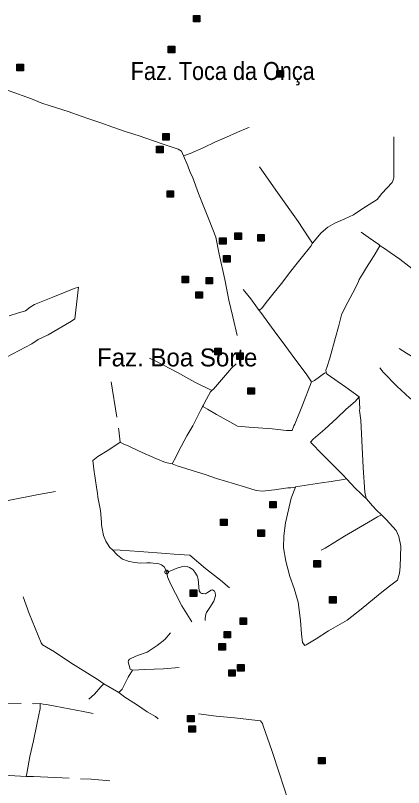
# Model space of a CAD drawing. Extents: x 393.5 to 446.9, y 8064.8 to 8120.4.
# Drawn here: x 404.99 to 408.44, y 8103.85 to 8110.72 of the extents above; entities that cross this region are included whole.
import ezdxf

# ---------------------------------------------------------------- set-up
doc = ezdxf.new("R2010")
doc.units = 0
doc.header["$LTSCALE"] = 0.064
doc.header["$PDMODE"] = 32
doc.header["$PDSIZE"] = 0.032
doc.linetypes.add('DOT_DASHED', pattern=[7.7, 5, -1.2, 0.3, -1.2])
doc.layers.add('2', color=7, linetype='Continuous', lineweight=25)
doc.layers.add('22', color=7, linetype='DOT_DASHED', lineweight=13)
doc.layers.add('61', color=7, linetype='Continuous')

msp = doc.modelspace()

# ---------------------------------------------------------------- hatches: boundary and pattern name
at = {"layer": '2'}
for points in [[(406.5725, 8110.7212), (406.6305, 8110.7212), (406.6305, 8110.6632), (406.5725, 8110.6632)], [(406.3481, 8110.4472), (406.4061, 8110.4472), (406.4061, 8110.3892), (406.3481, 8110.3892)], [(405.0009, 8110.2869), (405.0589, 8110.2869), (405.0589, 8110.2289), (405.0009, 8110.2289)], [(407.3152, 8110.2299), (407.3732, 8110.2299), (407.3732, 8110.1719), (407.3152, 8110.1719)], [(406.2995, 8109.6693), (406.3575, 8109.6693), (406.3575, 8109.6113), (406.2995, 8109.6113)], [(406.2434, 8109.557), (406.3014, 8109.557), (406.3014, 8109.499), (406.2434, 8109.499)], [(406.3382, 8109.1603), (406.3962, 8109.1603), (406.3962, 8109.1023), (406.3382, 8109.1023)], [(406.9409, 8108.7849), (406.9989, 8108.7849), (406.9989, 8108.7269), (406.9409, 8108.7269)], [(406.8043, 8108.7427), (406.8623, 8108.7427), (406.8623, 8108.6847), (406.8043, 8108.6847)], [(407.144, 8108.7706), (407.202, 8108.7706), (407.202, 8108.7126), (407.144, 8108.7126)], [(406.8404, 8108.5833), (406.8984, 8108.5833), (406.8984, 8108.5253), (406.8404, 8108.5253)], [(406.4713, 8108.3987), (406.5293, 8108.3987), (406.5293, 8108.3407), (406.4713, 8108.3407)], [(406.6849, 8108.3884), (406.7429, 8108.3884), (406.7429, 8108.3304), (406.6849, 8108.3304)], [(406.5937, 8108.2619), (406.6517, 8108.2619), (406.6517, 8108.2039), (406.5937, 8108.2039)], [(406.7619, 8107.7587), (406.8199, 8107.7587), (406.8199, 8107.7007), (406.7619, 8107.7007)], [(406.9581, 8107.7163), (407.0161, 8107.7163), (407.0161, 8107.6583), (406.9581, 8107.6583)], [(407.0561, 8107.407), (407.1141, 8107.407), (407.1141, 8107.349), (407.0561, 8107.349)], [(407.2518, 8106.3942), (407.3098, 8106.3942), (407.3098, 8106.3362), (407.2518, 8106.3362)], [(406.8131, 8106.2371), (406.8711, 8106.2371), (406.8711, 8106.1791), (406.8131, 8106.1791)], [(407.1464, 8106.1411), (407.2044, 8106.1411), (407.2044, 8106.0831), (407.1464, 8106.0831)], [(407.6446, 8105.8686), (407.7026, 8105.8686), (407.7026, 8105.8106), (407.6446, 8105.8106)], [(406.5431, 8105.607), (406.6011, 8105.607), (406.6011, 8105.549), (406.5431, 8105.549)], [(407.7832, 8105.5482), (407.8412, 8105.5482), (407.8412, 8105.4902), (407.7832, 8105.4902)], [(406.9878, 8105.357), (407.0458, 8105.357), (407.0458, 8105.299), (406.9878, 8105.299)], [(406.8443, 8105.2377), (406.9023, 8105.2377), (406.9023, 8105.1797), (406.8443, 8105.1797)], [(406.7987, 8105.1285), (406.8567, 8105.1285), (406.8567, 8105.0705), (406.7987, 8105.0705)], [(406.9656, 8104.942), (407.0236, 8104.942), (407.0236, 8104.884), (406.9656, 8104.884)], [(406.8863, 8104.8963), (406.9443, 8104.8963), (406.9443, 8104.8383), (406.8863, 8104.8383)], [(406.5196, 8104.4895), (406.5776, 8104.4895), (406.5776, 8104.4315), (406.5196, 8104.4315)], [(406.5313, 8104.3982), (406.5893, 8104.3982), (406.5893, 8104.3402), (406.5313, 8104.3402)], [(407.685, 8104.1159), (407.743, 8104.1159), (407.743, 8104.0579), (407.685, 8104.0579)]]:
    msp.add_hatch(color=256, dxfattribs=at).paths.add_polyline_path(points)

# ---------------------------------------------------------------- linework, layer by layer
for points in [[(406.5725, 8110.7212), (406.6305, 8110.7212), (406.6305, 8110.6632), (406.5725, 8110.6632)], [(406.3481, 8110.4472), (406.4061, 8110.4472), (406.4061, 8110.3892), (406.3481, 8110.3892)], [(405.0009, 8110.2869), (405.0589, 8110.2869), (405.0589, 8110.2289), (405.0009, 8110.2289)], [(407.3152, 8110.2299), (407.3732, 8110.2299), (407.3732, 8110.1719), (407.3152, 8110.1719)], [(406.2995, 8109.6693), (406.3575, 8109.6693), (406.3575, 8109.6113), (406.2995, 8109.6113)], [(406.2434, 8109.557), (406.3014, 8109.557), (406.3014, 8109.499), (406.2434, 8109.499)], [(406.3382, 8109.1603), (406.3962, 8109.1603), (406.3962, 8109.1023), (406.3382, 8109.1023)], [(406.9409, 8108.7849), (406.9989, 8108.7849), (406.9989, 8108.7269), (406.9409, 8108.7269)], [(406.8043, 8108.7427), (406.8623, 8108.7427), (406.8623, 8108.6847), (406.8043, 8108.6847)], [(407.144, 8108.7706), (407.202, 8108.7706), (407.202, 8108.7126), (407.144, 8108.7126)], [(406.8404, 8108.5833), (406.8984, 8108.5833), (406.8984, 8108.5253), (406.8404, 8108.5253)], [(406.4713, 8108.3987), (406.5293, 8108.3987), (406.5293, 8108.3407), (406.4713, 8108.3407)], [(406.6849, 8108.3884), (406.7429, 8108.3884), (406.7429, 8108.3304), (406.6849, 8108.3304)], [(406.5937, 8108.2619), (406.6517, 8108.2619), (406.6517, 8108.2039), (406.5937, 8108.2039)], [(406.7619, 8107.7587), (406.8199, 8107.7587), (406.8199, 8107.7007), (406.7619, 8107.7007)], [(406.9581, 8107.7163), (407.0161, 8107.7163), (407.0161, 8107.6583), (406.9581, 8107.6583)], [(407.0561, 8107.407), (407.1141, 8107.407), (407.1141, 8107.349), (407.0561, 8107.349)], [(407.2518, 8106.3942), (407.3098, 8106.3942), (407.3098, 8106.3362), (407.2518, 8106.3362)], [(406.8131, 8106.2371), (406.8711, 8106.2371), (406.8711, 8106.1791), (406.8131, 8106.1791)], [(407.1464, 8106.1411), (407.2044, 8106.1411), (407.2044, 8106.0831), (407.1464, 8106.0831)], [(407.6446, 8105.8686), (407.7026, 8105.8686), (407.7026, 8105.8106), (407.6446, 8105.8106)], [(406.5431, 8105.607), (406.6011, 8105.607), (406.6011, 8105.549), (406.5431, 8105.549)], [(407.7832, 8105.5482), (407.8412, 8105.5482), (407.8412, 8105.4902), (407.7832, 8105.4902)], [(406.9878, 8105.357), (407.0458, 8105.357), (407.0458, 8105.299), (406.9878, 8105.299)], [(406.8443, 8105.2377), (406.9023, 8105.2377), (406.9023, 8105.1797), (406.8443, 8105.1797)], [(406.7987, 8105.1285), (406.8567, 8105.1285), (406.8567, 8105.0705), (406.7987, 8105.0705)], [(406.9656, 8104.942), (407.0236, 8104.942), (407.0236, 8104.884), (406.9656, 8104.884)], [(406.8863, 8104.8963), (406.9443, 8104.8963), (406.9443, 8104.8383), (406.8863, 8104.8383)], [(406.5196, 8104.4895), (406.5776, 8104.4895), (406.5776, 8104.4315), (406.5196, 8104.4315)], [(406.5313, 8104.3982), (406.5893, 8104.3982), (406.5893, 8104.3402), (406.5313, 8104.3402)], [(407.685, 8104.1159), (407.743, 8104.1159), (407.743, 8104.0579), (407.685, 8104.0579)]]:
    msp.add_lwpolyline(points, close=True, dxfattribs=at)
at = {"layer": '22'}
for p, q in [((408.0468, 8107.3247), (408.0467, 8107.3262)), ((406.6529, 8107.24), (406.6548, 8107.2391)), ((406.3331, 8105.7669), (406.3336, 8105.7661)), ((405.7745, 8104.7708), (405.9083, 8104.6922)), ((405.6417, 8104.634), (405.6924, 8104.6772)), ((405.0845, 8103.947), (405.084, 8103.947))]:
    msp.add_line(p, q, dxfattribs=at)
for points in [[(406.0607, 8109.6581), (406.0233, 8109.6712), (405.9651, 8109.6881), (405.8537, 8109.7252), (405.7389, 8109.769), (405.6427, 8109.8011), (405.5735, 8109.8247), (405.457, 8109.8652), (405.2983, 8109.9175), (405.224, 8109.9411), (405.1312, 8109.9782), (404.9318, 8110.0502), (404.8896, 8110.067)], [(406.4851, 8109.471), (406.5419, 8109.4927), (406.6635, 8109.5467), (406.7614, 8109.5922), (406.8677, 8109.6378), (406.9589, 8109.6782), (407.0568, 8109.7204), (407.0669, 8109.7221)], [(406.3042, 8109.5761), (406.0811, 8109.6509), (406.0607, 8109.6581)], [(407.6308, 8108.693), (407.7091, 8108.787), (407.7681, 8108.8357), (407.8291, 8108.8723), (407.9186, 8108.9107), (407.9959, 8108.9473), (408.0447, 8108.9778), (408.1119, 8109.0245), (408.2059, 8109.0823), (408.2486, 8109.1351), (408.34, 8109.2345), (408.3522, 8109.2629), (408.3542, 8109.2812), (408.3563, 8109.3198), (408.3564, 8109.3745), (408.3565, 8109.6403)], [(406.4851, 8109.471), (406.4667, 8109.5114), (406.4363, 8109.5317), (406.3283, 8109.5654), (406.3042, 8109.5761)], [(406.5294, 8109.3649), (406.5233, 8109.381), (406.4851, 8109.471)], [(406.9609, 8107.8719), (406.9221, 8108.0389), (406.8883, 8108.1873), (406.8502, 8108.3718), (406.8023, 8108.5966), (406.7703, 8108.7468), (406.711, 8108.8971), (406.6169, 8109.1353), (406.5662, 8109.274), (406.5443, 8109.3263), (406.5294, 8109.3649)], [(407.159, 8109.3746), (407.3205, 8109.146), (407.5029, 8108.886), (407.5998, 8108.7418), (407.6308, 8108.693)], [(408.2326, 8108.6702), (408.2212, 8108.6807), (408.1265, 8108.7471), (408.0645, 8108.7916)], [(407.1566, 8108.0952), (407.1843, 8108.1188), (407.2316, 8108.1796), (407.2788, 8108.2403), (407.3666, 8108.3499), (407.4189, 8108.4174), (407.4713, 8108.4849), (407.5321, 8108.5591), (407.6165, 8108.667), (407.6308, 8108.693)], [(407.7526, 8107.5452), (407.7515, 8107.5639), (407.7578, 8107.5876), (407.7853, 8107.6699), (407.8365, 8107.8533), (407.8623, 8107.9497), (407.8885, 8108.0558), (407.9222, 8108.1232), (407.9897, 8108.2504), (408.0377, 8108.3451), (408.048, 8108.3713), (408.0775, 8108.4179), (408.1137, 8108.4766), (408.1599, 8108.5527), (408.1893, 8108.6001), (408.2323, 8108.6697), (408.2326, 8108.6702)], [(408.2326, 8108.6702), (408.2712, 8108.6457), (408.3228, 8108.6099), (408.4084, 8108.5514), (408.542, 8108.4464), (408.5883, 8108.4211), (408.639, 8108.387), (408.7159, 8108.3337), (408.7612, 8108.3029)], [(404.9089, 8107.6776), (405.1355, 8107.7987), (405.189, 8107.8348), (405.2787, 8107.8789), (405.4884, 8107.9989), (405.5168, 8108.0193), (405.5482, 8108.3023), (405.5105, 8108.2898), (405.3201, 8108.2143), (405.1572, 8108.1483), (405.1178, 8108.1247), (405.0785, 8108.0901), (405.0077, 8108.0697), (404.9322, 8108.0461)], [(407.1566, 8108.0952), (407.0817, 8108.1969), (407.031, 8108.2644), (407.0142, 8108.2813)], [(407.1566, 8108.0952), (407.1708, 8108.076), (407.29, 8107.9137), (407.3947, 8107.7752), (407.4746, 8107.6629), (407.5745, 8107.5294), (407.622, 8107.4583), (407.625, 8107.4597)], [(408.4043, 8107.7547), (408.4696, 8107.7146), (408.5968, 8107.6362), (408.643, 8107.6097)], [(406.1803, 8107.6703), (406.2365, 8107.644), (406.4295, 8107.5409), (406.5849, 8107.4567), (406.7358, 8107.3818)], [(406.9515, 8107.6188), (406.9115, 8107.5809), (406.7518, 8107.3948), (406.7383, 8107.3838), (406.7358, 8107.3818)], [(407.625, 8107.4597), (407.6482, 8107.4707), (407.739, 8107.5364), (407.7528, 8107.5414), (407.7526, 8107.5452)], [(408.0467, 8107.3262), (408.0467, 8107.3263), (407.9294, 8107.4129), (407.7628, 8107.5289), (407.7534, 8107.5407), (407.7528, 8107.5414)], [(408.2302, 8107.5827), (408.2614, 8107.5441), (408.3808, 8107.421), (408.4981, 8107.3142), (408.5664, 8107.2622), (408.6451, 8107.2207), (408.755, 8107.1806), (408.8753, 8107.1347), (409.0113, 8107.0785), (409.0133, 8107.0777)], [(405.8388, 8107.4601), (405.9081, 8107.0286), (405.919, 8106.9219)], [(407.4732, 8107.0811), (407.5429, 8107.2521), (407.622, 8107.4583)], [(406.7358, 8107.3818), (406.7238, 8107.3688), (406.6709, 8107.2725), (406.6619, 8107.2519), (406.6529, 8107.24)], [(407.9315, 8107.2149), (408.0109, 8107.2847), (408.0468, 8107.3247)], [(408.1109, 8106.4184), (408.1106, 8106.4214), (408.0967, 8106.478), (408.0819, 8106.6961), (408.07, 8106.9364), (408.0604, 8107.1175), (408.0508, 8107.2049), (408.0521, 8107.2211), (408.0468, 8107.3247)], [(406.6529, 8107.236), (406.6354, 8107.2042), (406.5654, 8107.0684), (406.5135, 8106.9785), (406.4395, 8106.8387), (406.4144, 8106.7895), (406.383, 8106.7303), (406.3822, 8106.7288)], [(406.6574, 8107.2442), (406.6563, 8107.2422), (406.6561, 8107.2418), (406.6553, 8107.2404), (406.6529, 8107.236)], [(406.6548, 8107.2391), (406.698, 8107.217), (406.7783, 8107.1682), (406.897, 8107.1035), (406.9629, 8107.0647), (406.9992, 8107.0631)], [(407.9323, 8106.5972), (407.9108, 8106.6215), (407.724, 8106.8106), (407.6141, 8106.9229), (407.6383, 8106.9496), (407.7422, 8107.0386), (407.8476, 8107.1366), (407.9315, 8107.2149)], [(406.9992, 8107.0631), (407.0641, 8107.0563), (407.2731, 8107.0423), (407.3996, 8107.0269), (407.4515, 8107.0269), (407.4664, 8107.067), (407.4732, 8107.0811)], [(405.919, 8106.9219), (405.8205, 8106.8535), (405.7223, 8106.7955), (405.6771, 8106.7593), (405.6897, 8106.6572)], [(406.3822, 8106.7288), (406.3229, 8106.7402), (406.2364, 8106.7777), (406.0891, 8106.8409), (405.9974, 8106.8861), (405.9461, 8106.9064), (405.9207, 8106.9209), (405.9192, 8106.9218), (405.919, 8106.9219)], [(406.3822, 8106.7288), (406.4287, 8106.712), (406.6857, 8106.6318), (406.7781, 8106.5988), (406.9385, 8106.5499), (407.035, 8106.5217), (407.13, 8106.4905), (407.1864, 8106.4861), (407.2933, 8106.4964), (407.4136, 8106.5142), (407.4397, 8106.5167), (407.479, 8106.5229), (407.4804, 8106.5231)], [(405.6897, 8106.6572), (405.6905, 8106.6415), (405.6982, 8106.6015), (405.7124, 8106.5008), (405.7179, 8106.4686)], [(407.4804, 8106.5231), (407.7104, 8106.5607), (407.7965, 8106.5726), (407.9064, 8106.5889), (407.9331, 8106.5963)], [(407.9331, 8106.5963), (407.9326, 8106.5968), (407.9323, 8106.5972)], [(407.9331, 8106.5963), (408.0144, 8106.5089), (408.059, 8106.4674), (408.0857, 8106.4407), (408.1109, 8106.4184)], [(407.479, 8106.5229), (407.442, 8106.4242), (407.3915, 8106.2031), (407.3752, 8106.0874), (407.3722, 8105.9806), (407.3939, 8105.8619), (407.4288, 8105.7255), (407.4674, 8105.6202), (407.5038, 8105.4986), (407.5246, 8105.3354), (407.5335, 8105.2167), (407.5424, 8105.1381), (407.5647, 8105.1129), (407.5766, 8105.1188), (407.6642, 8105.1707), (407.7755, 8105.2434), (407.9403, 8105.3384), (408.0659, 8105.4362), (408.2331, 8105.575), (408.3163, 8105.6402), (408.389, 8105.6936), (408.4054, 8105.7545), (408.4128, 8105.8123), (408.4179, 8105.9963), (408.4008, 8106.0809), (408.3756, 8106.1358), (408.2865, 8106.2322), (408.2456, 8106.2753), (408.2443, 8106.2766)], [(404.3893, 8105.8512), (404.3578, 8105.8982), (404.2273, 8106.0967), (404.0919, 8106.3017), (404.0635, 8106.3602), (404.0601, 8106.3835), (404.0702, 8106.4152), (404.0936, 8106.4353), (404.1186, 8106.4369), (404.1637, 8106.4336), (404.2071, 8106.4119), (404.3792, 8106.3134), (404.4193, 8106.3084), (404.8607, 8106.3883), (404.9392, 8106.4067), (405.1948, 8106.4551), (405.3451, 8106.4818)], [(405.7179, 8106.4686), (405.7228, 8106.4329), (405.746, 8106.3129), (405.7542, 8106.2097)], [(408.1109, 8106.4184), (408.1659, 8106.3546), (408.2027, 8106.3181), (408.2443, 8106.2766)], [(407.7095, 8105.9592), (407.7452, 8105.9785), (407.9168, 8106.0851), (408.1653, 8106.2306), (408.2114, 8106.2573), (408.2443, 8106.2766)], [(405.7542, 8106.2097), (405.7537, 8106.1868), (405.7589, 8106.1545), (405.7695, 8106.1048)], [(405.7695, 8106.1048), (405.7716, 8106.0903), (405.7923, 8106.0412), (405.8285, 8105.9844), (405.8498, 8105.9656), (405.8503, 8105.9652)], [(406.3272, 8105.9317), (406.0915, 8105.9474), (405.9188, 8105.9613), (405.8544, 8105.965), (405.8503, 8105.9652)], [(406.1678, 8105.8477), (406.1561, 8105.8469), (406.1006, 8105.8443), (406.0489, 8105.8495), (405.9921, 8105.8624), (405.9417, 8105.8818), (405.8968, 8105.9174), (405.8503, 8105.9652)], [(406.8936, 8105.6254), (406.813, 8105.6931), (406.68, 8105.7977), (406.5392, 8105.9164), (406.401, 8105.9255), (406.3272, 8105.9317)], [(406.3331, 8105.7669), (406.3256, 8105.7846), (406.3111, 8105.8108), (406.2892, 8105.8288), (406.2646, 8105.8379), (406.1888, 8105.8477), (406.1678, 8105.8477)], [(406.6764, 8105.3335), (406.6764, 8105.3529), (406.6816, 8105.3903), (406.6894, 8105.4058), (406.7178, 8105.451), (406.7527, 8105.5065), (406.7695, 8105.5529), (406.7669, 8105.5852), (406.7591, 8105.5968), (406.741, 8105.6071), (406.7294, 8105.6058), (406.6984, 8105.5826), (406.679, 8105.571), (406.6597, 8105.5736), (406.648, 8105.5749), (406.6364, 8105.5813), (406.6235, 8105.5981), (406.6132, 8105.7026), (406.6054, 8105.731), (406.5834, 8105.7646), (406.5654, 8105.7878), (406.5382, 8105.8072), (406.515, 8105.8162), (406.4904, 8105.8175), (406.4336, 8105.8033), (406.3618, 8105.7743), (406.3335, 8105.767), (406.3331, 8105.7669)], [(406.3336, 8105.7661), (406.3348, 8105.7641), (406.3354, 8105.7631)], [(406.3354, 8105.7631), (406.3357, 8105.7625), (406.3426, 8105.7247), (406.3717, 8105.6541), (406.4114, 8105.5738), (406.4699, 8105.4654), (406.5589, 8105.3232)], [(405.0572, 8105.5454), (405.1106, 8105.3963), (405.2177, 8105.1352), (405.2286, 8105.1171), (405.3359, 8105.0553), (405.4802, 8104.9579), (405.7153, 8104.8128), (405.7745, 8104.7708)], [(406.102, 8105.0312), (406.1594, 8105.0533), (406.2485, 8105.1115), (406.3162, 8105.1661), (406.3693, 8105.225)], [(406.031, 8104.8909), (406.0085, 8104.9026), (405.9919, 8104.9655), (405.9942, 8104.9785), (406.0038, 8104.9916), (406.0596, 8105.0177), (406.0845, 8105.0248), (406.102, 8105.0312)], [(405.9083, 8104.6922), (405.9379, 8104.7239), (405.9915, 8104.8289), (406.031, 8104.8909), (406.031, 8104.891), (406.0316, 8104.8919)], [(406.4444, 8104.9148), (406.3068, 8104.9053), (406.1392, 8104.8978), (406.0334, 8104.8911), (406.031, 8104.8909)], [(405.6924, 8104.6772), (405.7478, 8104.744), (405.7745, 8104.7708)], [(405.9083, 8104.6922), (405.9609, 8104.6513), (406.0641, 8104.5864), (406.1615, 8104.5215), (406.2342, 8104.4795), (406.259, 8104.4584)], [(404.0627, 8104.2571), (404.1245, 8104.2882), (404.3013, 8104.4034), (404.5066, 8104.5294), (404.6327, 8104.6093), (404.7203, 8104.6016), (405.1515, 8104.594), (405.2069, 8104.5955)], [(405.0845, 8103.947), (405.0883, 8103.9737), (405.1177, 8104.1239), (405.15, 8104.2621), (405.1777, 8104.4096), (405.2076, 8104.5525), (405.2092, 8104.5709), (405.2072, 8104.5922), (405.2069, 8104.5955)], [(405.6809, 8104.508), (405.5902, 8104.5249), (405.3427, 8104.571), (405.2658, 8104.5863), (405.2351, 8104.5894), (405.2069, 8104.5955)], [(406.6159, 8104.5029), (406.7733, 8104.4829), (406.9385, 8104.4669), (407.1703, 8104.4403), (407.1863, 8104.4164), (407.1918, 8104.3959)], [(407.1918, 8104.3959), (407.2696, 8104.1762), (407.3385, 8103.9687), (407.4147, 8103.7322), (407.4411, 8103.6611), (407.4425, 8103.6572)], [(405.084, 8103.947), (404.7985, 8103.9624), (404.6355, 8103.9655), (404.6151, 8103.6837), (404.5882, 8103.3201)], [(405.0845, 8103.947), (405.1475, 8103.9455), (405.6634, 8103.9209), (405.8269, 8103.9085)]]:
    msp.add_lwpolyline(points, dxfattribs=at)
msp.add_point((406.3336, 8105.7661), dxfattribs=at)

# ---------------------------------------------------------------- texts
at = {"layer": '61', "width": 0.9}
msp.add_text('Faz. Toca da Onça', height=0.16, dxfattribs=at).set_placement((406.014, 8110.1468))
at = {"layer": '61'}
msp.add_text('Faz. Boa Sorte', height=0.16, dxfattribs=at).set_placement((405.7139, 8107.5965))

doc.saveas('drawing.dxf')
